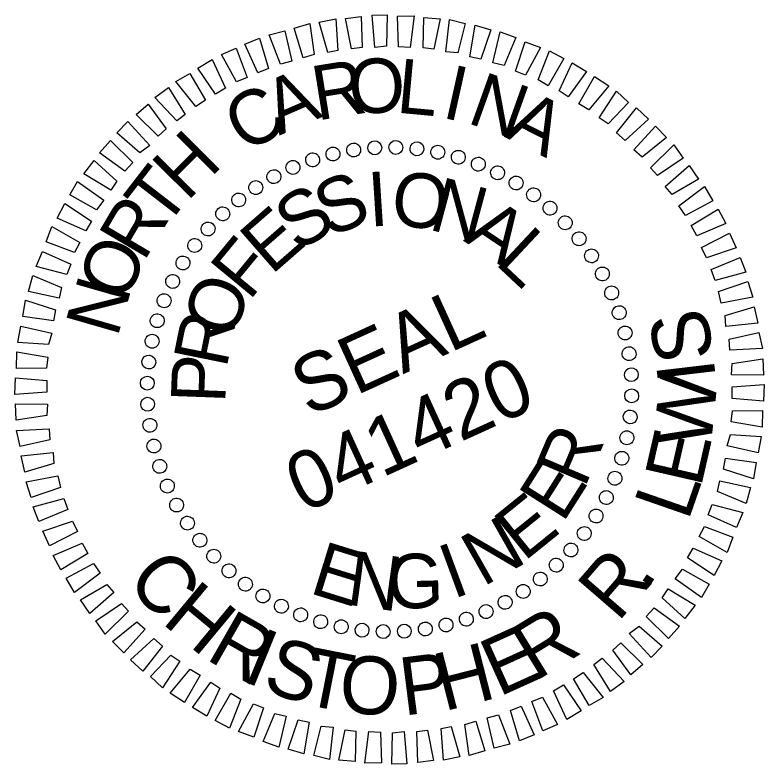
# Model space of a CAD drawing. Extents: x 2249053 to 2251039, y 663030 to 664800.
# Drawn here: x 2250902.6 to 2250980.1, y 664722.3 to 664799.9 of the extents above; entities that cross this region are included whole.
import ezdxf

# ---------------------------------------------------------------- set-up
doc = ezdxf.new("R2010")
doc.units = 0
doc.layers.add('Sheet PE Seal Cell', color=7, linetype='Continuous')

msp = doc.modelspace()

# ---------------------------------------------------------------- linework, layer by layer
at = {"layer": 'Sheet PE Seal Cell'}
for p, q in [((2250935.508, 664785.504), (2250935.508, 664785.504)), ((2250937.605, 664785.965), (2250937.605, 664785.965)), ((2250939.807, 664786.199), (2250939.807, 664786.199)), ((2250942, 664786.209), (2250942, 664786.209)), ((2250944.189, 664786.108), (2250944.189, 664786.108)), ((2250946.345, 664785.717), (2250946.345, 664785.717)), ((2250933.406, 664784.931), (2250933.406, 664784.931)), ((2250948.497, 664785.214), (2250948.497, 664785.214)), ((2250931.342, 664784.155), (2250931.342, 664784.155)), ((2250950.53, 664784.492), (2250950.53, 664784.492)), ((2250929.361, 664783.197), (2250929.361, 664783.197)), ((2250952.579, 664783.612), (2250952.579, 664783.612)), ((2250954.442, 664782.538), (2250954.442, 664782.538)), ((2250927.529, 664782.033), (2250927.529, 664782.033)), ((2250956.277, 664781.286), (2250956.277, 664781.286)), ((2250925.693, 664780.756), (2250925.693, 664780.756)), ((2250924.031, 664779.34), (2250924.031, 664779.34)), ((2250957.995, 664779.926), (2250957.995, 664779.926)), ((2250922.542, 664777.782), (2250922.542, 664777.782)), ((2250959.552, 664778.438), (2250959.552, 664778.438)), ((2250960.969, 664776.776), (2250960.969, 664776.776)), ((2250921.183, 664776.064), (2250921.183, 664776.064)), ((2250962.245, 664774.94), (2250962.245, 664774.94)), ((2250919.931, 664774.229), (2250919.931, 664774.229)), ((2250963.41, 664773.108), (2250963.41, 664773.108)), ((2250918.856, 664772.366), (2250918.856, 664772.366)), ((2250964.368, 664771.126), (2250964.368, 664771.126)), ((2250917.977, 664770.317), (2250917.977, 664770.317)), ((2250965.143, 664769.062), (2250965.143, 664769.062)), ((2250917.255, 664768.285), (2250917.255, 664768.285)), ((2250965.716, 664766.961), (2250965.716, 664766.961)), ((2250916.752, 664766.132), (2250916.752, 664766.132)), ((2250966.178, 664764.863), (2250966.178, 664764.863)), ((2250916.361, 664763.976), (2250916.361, 664763.976)), ((2250966.412, 664762.662), (2250966.412, 664762.662)), ((2250916.259, 664761.787), (2250916.259, 664761.787)), ((2250941.341, 664761.128), (2250941.341, 664761.128)), ((2250966.422, 664760.469), (2250966.422, 664760.469)), ((2250916.27, 664759.594), (2250916.27, 664759.594)), ((2250966.321, 664758.28), (2250966.321, 664758.28)), ((2250916.504, 664757.393), (2250916.504, 664757.393)), ((2250965.929, 664756.123), (2250965.929, 664756.123)), ((2250916.965, 664755.295), (2250916.965, 664755.295)), ((2250965.427, 664753.971), (2250965.427, 664753.971)), ((2250917.538, 664753.194), (2250917.538, 664753.194)), ((2250964.704, 664751.939), (2250964.704, 664751.939)), ((2250918.314, 664751.129), (2250918.314, 664751.129)), ((2250963.825, 664749.889), (2250963.825, 664749.889)), ((2250919.271, 664749.148), (2250919.271, 664749.148)), ((2250962.751, 664748.026), (2250962.751, 664748.026)), ((2250920.436, 664747.316), (2250920.436, 664747.316)), ((2250961.499, 664746.192), (2250961.499, 664746.192)), ((2250921.712, 664745.48), (2250921.712, 664745.48)), ((2250960.139, 664744.473), (2250960.139, 664744.473)), ((2250923.129, 664743.818), (2250923.129, 664743.818)), ((2250958.651, 664742.916), (2250958.651, 664742.916)), ((2250924.686, 664742.33), (2250924.686, 664742.33)), ((2250956.989, 664741.499), (2250956.989, 664741.499)), ((2250926.405, 664740.97), (2250926.405, 664740.97)), ((2250928.239, 664739.718), (2250928.239, 664739.718)), ((2250955.152, 664740.223), (2250955.152, 664740.223)), ((2250953.32, 664739.059), (2250953.32, 664739.059)), ((2250930.102, 664738.644), (2250930.102, 664738.644)), ((2250932.151, 664737.764), (2250932.151, 664737.764)), ((2250951.339, 664738.101), (2250951.339, 664738.101)), ((2250934.184, 664737.042), (2250934.184, 664737.042)), ((2250947.173, 664736.752), (2250947.173, 664736.752)), ((2250949.275, 664737.325), (2250949.275, 664737.325)), ((2250936.336, 664736.539), (2250936.336, 664736.539)), ((2250938.492, 664736.148), (2250938.492, 664736.148)), ((2250940.682, 664736.047), (2250940.682, 664736.047)), ((2250942.875, 664736.057), (2250942.875, 664736.057)), ((2250945.076, 664736.291), (2250945.076, 664736.291))]:
    msp.add_line(p, q, dxfattribs=at)
for points in [[(2250934.948, 664796.018), (2250934.055, 664799.183), (2250935.768, 664799.524), (2250936.007, 664796.226)], [(2250937.401, 664796.422), (2250936.798, 664799.553), (2250938.416, 664799.741), (2250938.502, 664796.538)], [(2250939.822, 664796.536), (2250939.562, 664799.879), (2250941.085, 664799.913), (2250941.013, 664796.694)], [(2250942.263, 664796.604), (2250942.177, 664799.807), (2250943.878, 664799.813), (2250943.492, 664796.56)], [(2250944.833, 664796.511), (2250944.88, 664799.665), (2250946.597, 664799.513), (2250945.946, 664796.359)], [(2250947.167, 664796.091), (2250947.557, 664799.456), (2250949.176, 664799.04), (2250948.417, 664796.002)], [(2250932.399, 664795.461), (2250931.482, 664798.559), (2250933.087, 664799.016), (2250933.553, 664795.822)], [(2250949.655, 664795.577), (2250950.198, 664798.846), (2250951.837, 664798.384), (2250950.809, 664795.333)], [(2250930.049, 664794.83), (2250928.884, 664797.87), (2250930.51, 664798.281), (2250931.224, 664795.145)], [(2250952.026, 664794.954), (2250952.814, 664798.17), (2250954.403, 664797.576), (2250953.202, 664794.665)], [(2250927.712, 664793.93), (2250926.365, 664796.887), (2250927.887, 664797.526), (2250928.825, 664794.382)], [(2250954.39, 664794.108), (2250955.372, 664797.138), (2250956.962, 664796.543), (2250955.404, 664793.691)], [(2250925.508, 664792.98), (2250923.932, 664795.834), (2250925.455, 664796.472), (2250926.62, 664793.432)], [(2250956.729, 664793.196), (2250957.889, 664796.197), (2250959.404, 664795.404), (2250957.78, 664792.576)], [(2250923.336, 664791.716), (2250921.509, 664794.4), (2250922.973, 664795.287), (2250924.366, 664792.35)], [(2250958.902, 664792.043), (2250960.261, 664794.97), (2250961.727, 664794.044), (2250959.842, 664791.427)], [(2250921.277, 664790.448), (2250919.222, 664793.028), (2250920.661, 664793.848), (2250922.307, 664791.082)], [(2250960.935, 664790.717), (2250962.559, 664793.544), (2250964.045, 664792.573), (2250961.987, 664790.097)], [(2250919.321, 664788.952), (2250917.059, 664791.383), (2250918.461, 664792.406), (2250920.173, 664789.615)], [(2250963.031, 664789.254), (2250964.853, 664792.007), (2250966.087, 664790.866), (2250963.971, 664788.638)], [(2250917.406, 664787.365), (2250915.116, 664789.618), (2250916.34, 664790.671), (2250918.217, 664788.119)], [(2250964.832, 664787.712), (2250966.895, 664790.3), (2250968.149, 664789.114), (2250965.743, 664786.918)], [(2250915.509, 664785.621), (2250913.123, 664787.721), (2250914.239, 664788.889), (2250916.522, 664786.413)], [(2250966.626, 664785.947), (2250968.862, 664788.394), (2250970.005, 664787.212), (2250967.516, 664785.199)], [(2250913.942, 664783.754), (2250911.325, 664785.638), (2250912.445, 664786.918), (2250914.757, 664784.619)], [(2250968.349, 664784.095), (2250970.784, 664786.468), (2250971.741, 664785.091), (2250969.103, 664783.284)], [(2250912.483, 664781.77), (2250909.68, 664783.46), (2250910.759, 664784.831), (2250913.099, 664782.71)], [(2250969.89, 664782.159), (2250972.362, 664784.33), (2250973.34, 664782.907), (2250970.598, 664781.328)], [(2250911, 664779.72), (2250908.259, 664781.274), (2250909.048, 664782.677), (2250911.752, 664780.723)], [(2250971.295, 664780.162), (2250973.962, 664782.147), (2250974.803, 664780.662), (2250971.974, 664779.153)], [(2250909.893, 664777.568), (2250906.941, 664778.86), (2250907.734, 664780.375), (2250910.488, 664778.553)], [(2250972.563, 664778.103), (2250975.354, 664779.814), (2250976.15, 664778.309), (2250973.151, 664777.052)], [(2250908.716, 664775.328), (2250905.801, 664776.417), (2250906.396, 664778.007), (2250909.29, 664776.359)], [(2250973.645, 664775.848), (2250976.54, 664777.332), (2250977.245, 664775.785), (2250974.142, 664774.756)], [(2250907.94, 664773.051), (2250904.769, 664773.859), (2250905.43, 664775.424), (2250908.336, 664774.111)], [(2250974.636, 664773.553), (2250977.635, 664774.809), (2250978.228, 664773.266), (2250975.043, 664772.419)], [(2250907.135, 664770.597), (2250903.961, 664771.293), (2250904.422, 664772.932), (2250907.399, 664771.706)], [(2250975.404, 664771.265), (2250978.44, 664772.319), (2250978.963, 664770.689), (2250975.674, 664770.069)], [(2250906.558, 664768.246), (2250903.396, 664768.673), (2250903.659, 664770.386), (2250906.756, 664769.38)], [(2250976.097, 664768.779), (2250979.084, 664769.7), (2250979.47, 664768.008), (2250976.169, 664767.657)], [(2250906.022, 664765.804), (2250902.852, 664766.008), (2250903.182, 664767.696), (2250906.377, 664766.954)], [(2250976.501, 664766.325), (2250979.591, 664767.019), (2250979.957, 664765.373), (2250976.572, 664765.204)], [(2250905.822, 664763.35), (2250902.71, 664763.305), (2250902.75, 664765.027), (2250905.974, 664764.463)], [(2250976.814, 664763.83), (2250980.008, 664764.297), (2250980.059, 664762.617), (2250976.748, 664762.647)], [(2250905.866, 664760.842), (2250902.568, 664760.603), (2250902.608, 664762.324), (2250905.864, 664762.05)], [(2250976.816, 664761.414), (2250980.114, 664761.653), (2250980.074, 664759.931), (2250976.817, 664760.205)], [(2250905.868, 664758.425), (2250902.674, 664757.959), (2250902.623, 664759.639), (2250905.933, 664759.609)], [(2250976.86, 664758.906), (2250979.971, 664758.95), (2250979.932, 664757.229), (2250976.707, 664757.793)], [(2250906.181, 664755.93), (2250903.09, 664755.236), (2250902.724, 664756.883), (2250906.109, 664757.052)], [(2250976.659, 664756.452), (2250979.829, 664756.248), (2250979.5, 664754.56), (2250976.304, 664755.301)], [(2250906.584, 664753.477), (2250903.598, 664752.556), (2250903.211, 664754.248), (2250906.513, 664754.598)], [(2250976.123, 664754.01), (2250979.285, 664753.583), (2250979.022, 664751.869), (2250975.926, 664752.876)], [(2250907.278, 664750.991), (2250904.241, 664749.937), (2250903.718, 664751.567), (2250907.008, 664752.186)], [(2250975.546, 664751.659), (2250978.721, 664750.963), (2250978.259, 664749.324), (2250975.283, 664750.55)], [(2250908.045, 664748.703), (2250905.047, 664747.446), (2250904.453, 664748.989), (2250907.639, 664749.837)], [(2250974.742, 664749.205), (2250977.912, 664748.396), (2250977.252, 664746.832), (2250974.345, 664748.145)], [(2250909.037, 664746.407), (2250906.141, 664744.923), (2250905.436, 664746.47), (2250908.539, 664747.499)], [(2250973.966, 664746.928), (2250976.88, 664745.838), (2250976.286, 664744.249), (2250973.392, 664745.897)], [(2250910.119, 664744.153), (2250907.327, 664742.442), (2250906.531, 664743.947), (2250909.53, 664745.204)], [(2250972.789, 664744.688), (2250975.74, 664743.396), (2250974.947, 664741.88), (2250972.194, 664743.703)], [(2250911.387, 664742.094), (2250908.72, 664740.109), (2250907.878, 664741.594), (2250910.707, 664743.103)], [(2250971.682, 664742.535), (2250974.423, 664740.982), (2250973.634, 664739.578), (2250970.93, 664741.533)], [(2250912.792, 664740.096), (2250910.319, 664737.926), (2250909.341, 664739.348), (2250912.083, 664740.927)], [(2250970.198, 664740.486), (2250973.001, 664738.796), (2250971.922, 664737.425), (2250969.582, 664739.546)], [(2250914.333, 664738.161), (2250911.898, 664735.788), (2250910.94, 664737.165), (2250913.579, 664738.972)], [(2250968.739, 664738.502), (2250971.356, 664736.618), (2250970.236, 664735.338), (2250967.925, 664737.636)], [(2250916.056, 664736.309), (2250913.82, 664733.861), (2250912.676, 664735.044), (2250915.166, 664737.057)], [(2250967.173, 664736.634), (2250969.558, 664734.534), (2250968.442, 664733.367), (2250966.16, 664735.843)], [(2250917.849, 664734.544), (2250915.787, 664731.955), (2250914.532, 664733.142), (2250916.938, 664735.337)], [(2250965.275, 664734.89), (2250967.565, 664732.637), (2250966.342, 664731.585), (2250964.465, 664734.137)], [(2250919.651, 664733.002), (2250917.829, 664730.248), (2250916.594, 664731.389), (2250918.711, 664733.618)], [(2250963.361, 664733.304), (2250965.622, 664730.873), (2250964.22, 664729.849), (2250962.509, 664732.641)], [(2250921.746, 664731.539), (2250920.122, 664728.711), (2250918.636, 664729.682), (2250920.694, 664732.159)], [(2250961.405, 664731.808), (2250963.46, 664729.228), (2250962.02, 664728.407), (2250960.375, 664731.174)], [(2250923.779, 664730.213), (2250922.42, 664727.286), (2250920.955, 664728.211), (2250922.839, 664730.828)], [(2250959.345, 664730.54), (2250961.173, 664727.856), (2250959.709, 664726.969), (2250958.315, 664729.906)], [(2250925.953, 664729.06), (2250924.793, 664726.059), (2250923.277, 664726.852), (2250924.901, 664729.68)], [(2250957.174, 664729.276), (2250958.749, 664726.422), (2250957.227, 664725.783), (2250956.061, 664728.824)], [(2250928.291, 664728.148), (2250927.309, 664725.118), (2250925.72, 664725.712), (2250927.277, 664728.565)], [(2250954.969, 664728.326), (2250956.317, 664725.369), (2250954.795, 664724.73), (2250953.856, 664727.874)], [(2250930.655, 664727.302), (2250929.868, 664724.086), (2250928.278, 664724.68), (2250929.48, 664727.59)], [(2250952.632, 664727.426), (2250953.798, 664724.386), (2250952.172, 664723.974), (2250951.457, 664727.11)], [(2250933.027, 664726.679), (2250932.484, 664723.41), (2250930.845, 664723.872), (2250931.872, 664726.922)], [(2250950.282, 664726.795), (2250951.2, 664723.696), (2250949.595, 664723.24), (2250949.128, 664726.434)], [(2250935.514, 664726.164), (2250935.124, 664722.8), (2250933.506, 664723.216), (2250934.264, 664726.254)], [(2250937.848, 664725.744), (2250937.802, 664722.591), (2250936.084, 664722.743), (2250936.735, 664725.896)], [(2250945.28, 664725.834), (2250945.883, 664722.702), (2250944.265, 664722.515), (2250944.18, 664725.717)], [(2250947.734, 664726.238), (2250948.626, 664723.073), (2250946.914, 664722.732), (2250946.675, 664726.03)], [(2250940.418, 664725.652), (2250940.504, 664722.449), (2250938.803, 664722.443), (2250939.189, 664725.696)], [(2250942.86, 664725.72), (2250943.119, 664722.377), (2250941.597, 664722.342), (2250941.668, 664725.562)]]:
    msp.add_lwpolyline(points, close=True, dxfattribs=at)
for centre, major_axis in [((2250935.487, 664785.515), (-0.168, 0.7)), ((2250937.635, 664785.933), (-0.106, 0.712)), ((2250939.811, 664786.161), (-0.044, 0.719)), ((2250941.998, 664786.199), (0.019, 0.72)), ((2250944.181, 664786.047), (0.082, 0.715)), ((2250946.342, 664785.704), (0.144, 0.706)), ((2250933.384, 664784.912), (-0.228, 0.683)), ((2250948.465, 664785.175), (0.205, 0.69)), ((2250931.341, 664784.128), (-0.287, 0.66)), ((2250950.533, 664784.462), (0.264, 0.67)), ((2250929.374, 664783.169), (-0.344, 0.633)), ((2250952.532, 664783.572), (0.321, 0.644)), ((2250954.446, 664782.512), (0.376, 0.614)), ((2250927.499, 664782.042), (-0.397, 0.6)), ((2250956.26, 664781.288), (0.428, 0.579)), ((2250925.729, 664780.756), (-0.448, 0.563)), ((2250924.077, 664779.321), (-0.496, 0.522)), ((2250957.96, 664779.911), (0.477, 0.539)), ((2250922.557, 664777.747), (-0.539, 0.477)), ((2250959.534, 664778.391), (0.522, 0.496)), ((2250960.969, 664776.74), (0.563, 0.448)), ((2250921.181, 664776.047), (-0.579, 0.428)), ((2250962.255, 664774.97), (0.6, 0.397)), ((2250919.957, 664774.233), (-0.614, 0.376)), ((2250963.382, 664773.094), (0.633, 0.344)), ((2250918.896, 664772.319), (-0.644, 0.321)), ((2250964.341, 664771.128), (0.66, 0.287)), ((2250918.006, 664770.321), (-0.67, 0.264)), ((2250965.125, 664769.085), (0.683, 0.228)), ((2250917.294, 664768.252), (-0.69, 0.205)), ((2250965.728, 664766.982), (0.7, 0.168)), ((2250916.764, 664766.129), (-0.706, 0.144)), ((2250966.145, 664764.834), (0.712, 0.106)), ((2250916.422, 664763.968), (-0.715, 0.082)), ((2250966.374, 664762.658), (0.719, 0.044)), ((2250916.269, 664761.785), (-0.72, 0.019)), ((2250966.412, 664760.47), (0.72, -0.019)), ((2250916.307, 664759.598), (-0.719, -0.044)), ((2250966.259, 664758.288), (0.715, -0.082)), ((2250916.536, 664757.422), (-0.712, -0.106)), ((2250965.917, 664756.127), (0.706, -0.144)), ((2250916.953, 664755.274), (-0.7, -0.168)), ((2250965.388, 664754.004), (0.69, -0.205)), ((2250917.556, 664753.171), (-0.683, -0.228)), ((2250964.675, 664751.935), (0.67, -0.264)), ((2250918.34, 664751.128), (-0.66, -0.287)), ((2250963.785, 664749.936), (0.644, -0.321)), ((2250919.3, 664749.162), (-0.633, -0.344)), ((2250962.724, 664748.023), (0.614, -0.376)), ((2250920.426, 664747.286), (-0.6, -0.397)), ((2250961.501, 664746.209), (0.579, -0.428)), ((2250921.712, 664745.516), (-0.563, -0.448)), ((2250960.124, 664744.509), (0.539, -0.477)), ((2250923.148, 664743.865), (-0.522, -0.496)), ((2250958.604, 664742.935), (0.496, -0.522)), ((2250924.722, 664742.345), (-0.477, -0.539)), ((2250956.953, 664741.499), (0.448, -0.563)), ((2250926.422, 664740.968), (-0.428, -0.579)), ((2250928.236, 664739.744), (-0.376, -0.614)), ((2250955.183, 664740.213), (0.397, -0.6)), ((2250953.307, 664739.087), (0.344, -0.633)), ((2250930.149, 664738.683), (-0.321, -0.644)), ((2250951.341, 664738.128), (0.287, -0.66)), ((2250932.148, 664737.793), (-0.264, -0.67)), ((2250949.298, 664737.344), (0.228, -0.683)), ((2250934.217, 664737.081), (-0.205, -0.69)), ((2250947.195, 664736.741), (0.168, -0.7)), ((2250936.34, 664736.552), (-0.144, -0.706)), ((2250938.501, 664736.209), (-0.082, -0.715)), ((2250940.683, 664736.056), (-0.019, -0.72)), ((2250942.871, 664736.095), (0.044, -0.719)), ((2250945.047, 664736.323), (0.106, -0.712))]:
    msp.add_ellipse(centre, major_axis=major_axis, ratio=0.999708, dxfattribs=at)

# ---------------------------------------------------------------- texts
for s, height, rotation, p in [('R', 5.638, 9.11904, (2250933.821, 664788.966)), ('O', 5.638, 1.91911, (2250937.18, 664789.672)), ('L', 5.638, 354.71882, (2250941.951, 664789.813)), ('I', 5.638, 347.51808, (2250946.632, 664789.309)), ('A', 5.638, 23.51826, (2250929.916, 664787.406)), ('N', 5.639, 340.31685, (2250949.231, 664788.79)), ('C', 5.638, 30.71781, (2250926.446, 664785.495)), ('A', 5.639, 333.1151, (2250953.138, 664787.329)), ('H', 5.638, 45.11742, (2250920.359, 664780.524)), ('T', 5.638, 52.31772, (2250918.086, 664777.675)), ('S', 5.638, 22.39834, (2250935.061, 664776.838)), ('I', 5.638, 3.68755, (2250939.264, 664777.984)), ('O', 5.638, 354.33143, (2250941.374, 664778.177)), ('N', 5.639, 344.97455, (2250945.252, 664777.746)), ('S', 5.638, 31.75355, (2250931.806, 664775.3)), ('R', 5.639, 59.51845, (2250915.904, 664774.263)), ('E', 5.638, 41.10901, (2250929.102, 664772.914)), ('A', 5.639, 326.25821, (2250948.924, 664776.562)), ('L', 5.639, 316.89879, (2250952.129, 664774.231)), ('F', 5.638, 50.46498, (2250926.812, 664770.222)), ('O', 5.639, 66.71968, (2250914.05, 664770.011)), ('N', 5.639, 73.92144, (2250913.16, 664766.419)), ('O', 5.639, 69.17918, (2250925.032, 664766.169)), ('SEAL', 5.9982, 24.49794, (2250932.982, 664758.252)), ('S', 5.998, 100.55241, (2250974.987, 664764.529)), ('R', 5.639, 78.53759, (2250924.456, 664763.214)), ('P', 5.639, 87.89683, (2250924.327, 664759.639)), ('041420', 5.9982, 24.49794, (2250932.432, 664748.268)), ('I', 5.998, 96.75046, (2250975.139, 664762.291)), ('W', 5.998, 84.21639, (2250974.586, 664754.928)), ('R', 5.639, 66.97935, (2250961.532, 664750.822)), ('E', 5.998, 77.10705, (2250973.563, 664750.861)), ('E', 5.638, 57.62203, (2250959.276, 664747.212)), ('L', 5.998, 70.83229, (2250972.248, 664747.401)), ('E', 5.638, 38.9097, (2250955.261, 664743.24)), ('N', 5.638, 29.55433, (2250951.006, 664740.641)), ('E', 5.638, 342.77483, (2250932.907, 664740.086)), ('I', 5.638, 20.19914, (2250947.895, 664739.389)), ('N', 5.638, 352.1319, (2250936.756, 664738.873)), ('C', 5.998, 310.69992, (2250913.954, 664741.288)), ('G', 5.638, 1.48818, (2250941.147, 664738.402)), ('R', 5.998, 49.11789, (2250964.976, 664736.94)), ('.', 5.998, 56.59815, (2250967.924, 664740.223)), ('H', 5.998, 320.28207, (2250917.638, 664737.006)), ('R', 5.998, 31.43728, (2250956.513, 664730.904)), ('R', 5.998, 330.26605, (2250922.179, 664733.262)), ('E', 5.998, 24.32794, (2250952.656, 664729.259)), ('I', 5.998, 337.74631, (2250925.97, 664731.005)), ('S', 5.998, 341.54826, (2250928.001, 664730.052)), ('T', 5.998, 348.87397, (2250932.073, 664728.605)), ('H', 5.998, 14.34395, (2250946.96, 664727.78)), ('O', 5.998, 355.67421, (2250935.989, 664727.736)), ('P', 5.998, 7.23461, (2250942.789, 664727.341))]:
    msp.add_text(s, height=height, rotation=rotation, dxfattribs=at).set_placement(p)

doc.saveas('drawing.dxf')
